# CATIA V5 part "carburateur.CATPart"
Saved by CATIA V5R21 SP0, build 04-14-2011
Part number: carburateur
Material "Aluminium": density 2710 kg/m3, Young's modulus 7e+10 Pa, Poisson ratio 0.346, thermal expansion 2.36e-05 1/K
Material "Aluminium": density 2710 kg/m3, Young's modulus 7e+10 Pa, Poisson ratio 0.346, thermal expansion 2.36e-05 1/K
Bounding box of the stored display mesh (mm): x -7.747 to 7, y -20 to 18, z -16 to 12
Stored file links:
  C:\Users\Olivier\Desktop\redaction CATIA (local)\CATIA\DONNEES\Exercice assemblage 3 (Pompe de ventilation)\carburateur.CATPart
  C:\Program Files\Dassault Systemes\B21\win_b64\startup\materials\French\Catalog.CATMaterial
  C:\Users\Olivier\Desktop\redaction CATIA (local)\pompe à moteur de ventilation refait\Pompe_a_moteur_de_ventilation.CATProduct
  C:\Users\Olivier\Desktop\redaction CATIA (local)\pompe à moteur de ventilation refait\Ecrou a collerette M5.CATPart
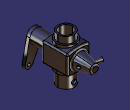
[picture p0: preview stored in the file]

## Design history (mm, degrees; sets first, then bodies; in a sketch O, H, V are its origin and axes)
Body1 (main body), material "Aluminium"
  Sketch1 on zx-plane, origin (0, 0, 0), H (-1, 0, 0), V (0, 0, 1)
    line L1 (7, 5.8379) -> (7, -5.8379)
    line L2 (-7, -5.8379) -> (-7, 5.8379)
    point P1 (7, 7)
    point P2 (7, -7)
    point P3 (-7, 7)
    arc A1 centre (0, -14.664) radius 21.664 from (-7, 5.8379) to (7, 5.8379) cw
    point P5 (-7, 5.8379)
    point P6 (7, 5.8379)
    point P7 (7, -5.8379)
    point P8 (-7, -5.8379)
    arc A2 centre (0, 14.664) radius 21.664 from (-7, -5.8379) to (7, -5.8379) ccw
    distance P1 P2 = 14
    distance P3 P1 = 14
    vertical: L1 V, L2 V
    equidistance: L1 L2 O
    symmetry: P6 P7 H, P5 P8 H, A1 A2 H
  Pad1: profile Sketch1, direction (0, 1, 0), length 8, mirrored extent
  Sketch2 on yz-plane, origin (0, 0, 0), H (0, 1, 0), V (0, 0, 1)
    projected line E1 (8, 5.8379) -> (8, -5.8379) from edge [face of Pad1 from Sketch1.L2 | end face of Pad1]
    projected line E2 (8, 5.0377) -> (8, 0) from edge [face of Pad1 from Sketch1.L2 | end face of Pad1]
    line L1 (8, 0) -> (18, 0)
    point P3 (8, 0)
    line L2 (18, 0) -> (18, 2.5)
    line L3 (18, 2.5) -> (8, 5.0377)
    point P6 (8, 5.0377)
    length L1 = 10
    length L2 = 2.5
    midpoint: P3 E1
    horizontal: L1 H
    vertical: L2 V
    coincidence: P6 E1
  Shaft1: profile Sketch2, axis Sketch2.L1, angle 360
  Sketch3 on start face of Pad1, origin (0, -8, 0), H (1, 0, 0), V (0, 0, 1)
    circle A1 centre (0, 0) radius 4.25
  Pad2: profile Sketch3, direction (0, -1, 0), length 10
  Sketch4 on end face of Pad2, origin (0, -18, 0), H (1, 0, 0), V (0, 0, 1)
    projected circle E1 centre (0, 0) radius 4.25 from edge [face of Pad2 from Sketch3.A1 | end face of Pad2]
    projected arc E2 centre (0, 0) radius 4.25 from (4.1613, 0.8638) to (-3.743, -2.0131) ccw from edge [face of Pad2 from Sketch3.A1 | end face of Pad2]
    circle A1 centre (4.7883, -13.1557) radius 1
    point P1 (4.7883, -13.1557)
    arc A2 centre (4.7883, -13.1557) radius 2.2354 from (2.8196, -14.2146) to (6.977, -12.7014) ccw
    line L1 (6.977, -12.7014) -> (4.1613, 0.8638)
    point P3 (4.1613, 0.8638)
    line L2 (2.8196, -14.2146) -> (-3.743, -2.0131)
    point P5 (-3.743, -2.0131)
    construction line L3 (0, 0) -> (4.7883, -13.1557)
    distance P1 O = 14
    angle L1 L2 = 16.547
    angle L3 H = 70
    tangency: L1 A2, L1 E1, L2 A2, L2 E1
    coincidence: E1 P3, E1 P5
    symmetry: L1 L2 L3
  Pad3: profile Sketch4, direction (0, -1, 0), length 2
  Sketch5 on xy-plane, origin (0, 0, 0), H (1, 0, 0), V (0, 1, 0)
    reference projected line E1 (-2.5, 18) -> (2.5, 18) from edge [face of Shaft1 from Sketch2.L3 | face of Shaft1 from Sketch2.L2]
    construction line L1 (-6.6056, 18) -> (-9.0298, 8.447)
    point P5 (-6.6056, 18)
    construction line L2 (-7.7542, 13.4735) -> (0, 11.5058)
    point P7 (-7.7542, 13.4735)
    point P9 (-7.1158, 15.9892)
    length L2 = 8
    coincidence: P5 E1, P7 L1, P9 L1
  Plane1: type Tangent, Support face of Shaft1 from Sketch2.L3, RefPoint Sketch5.P9
  Sketch6 on Plane1, origin (-10.4973, 2.6639, 0), H (0.246, 0.9693, 0), V (0, 0, 1)
    circle A1 centre (12.4304, 0) radius 1.25
    point P2 (11.982, 0)
  Pad4: profile Sketch6, direction (0.9693, -0.246, 0), up to the existing solid (limit type 2)
  Sketch7 on xy-plane, origin (0, 0, 0), H (1, 0, 0), V (0, 1, 0)
    circle A1 centre (0, 0) radius 6
    circle A2 centre (0, 0) radius 5
  MultiPad1: profile Sketch7, domains (length 12 / length 16; length 8 / length 8)
  Sketch8 on xy-plane, origin (0, 0, 0), H (1, 0, 0), V (0, 1, 0)
    circle A1 centre (0, 0) radius 4
  Pocket1: profile Sketch8, direction (0, 0, -1), length 26, mirrored extent
  Sketch9 on zx-plane, origin (0, 0, 0), H (-1, 0, 0), V (0, 0, 1)
    circle A1 centre (0, -13) radius 1.5
    point P1 (0, -13)
    reference projected line E1 (-6, -8) -> (6, -8) from edge [face of MultiPad1 | face of MultiPad1 from Sketch7.A1]
    distance E1 P1 = 5
    coincidence: P1 V
  Pocket2: profile Sketch9, direction (0, -1, 0), length 12, mirrored extent
  Sketch10 on xy-plane, origin (0, 0, 0), H (1, 0, 0), V (0, 1, 0)
    projected line E1 (-7, 8) -> (7, 8) from edge [face of Pad1 from Sketch1.A1 | end face of Pad1]
    projected line E2 (-3.7002, 8) -> (-1.6252, 8) from edge [face of Pad1 from Sketch1.A1 | end face of Pad1]
    projected line E3 (-2.5, 18) -> (2.5, 18) from edge [face of Shaft1 from Sketch2.L3 | face of Shaft1 from Sketch2.L2]
    line L1 (0, 16.8198) -> (0, 2.4964)
    point P5 (0, 18)
    line L2 (-1.6087, 16.8198) -> (-3.7002, 8)
    point P6 (-3.7002, 8)
    line L3 (-1.6252, 8) -> (-1.6252, 2.4964)
    point P7 (-1.6252, 8)
    line L4 (-1.6252, 2.4964) -> (0, 2.4964)
    line L5 (0, 16.8198) -> (-1.6087, 16.8198)
    midpoint: P5 E3
    vertical: L1 V, L3 V
    coincidence: P6 E1, P7 E1
    horizontal: L4 H, L5 H
  Groove1: profile Sketch10, axis Sketch10.L1, angle 360
  Sketch11 on start face of Pad4, origin (-10.4973, 2.6639, 0), H (-0.246, -0.9693, 0), V (0, 0, 1)
    reference projected circle E1 centre (-12.4304, 0) radius 1.25 from edge [start face of Pad4 | face of Pad4 from Sketch6.A1]
    circle A1 centre (-12.4304, 0) radius 1
    point P1 (-12.4304, 0)
    concentricity: P1 E1
  Pocket3: profile Sketch11, direction (0.9693, -0.246, 0), length 26
  Fillet1: radius 1, on edge [face of Pad1 from Sketch1.A1 | end face of Pad1]; edge [face of Pad1 from Sketch1.L2 | end face of Pad1]; edge [face of Pad1 from Sketch1.A2 | end face of Pad1]; edge [face of Pad1 from Sketch1.L1 | end face of Pad1]; edge [face of Pad1 from Sketch1.A1 | face of Pad1 from Sketch1.L1]; edge [face of Pad1 from Sketch1.L2 | face of Pad1 from Sketch1.A1]; edge [face of Pad1 from Sketch1.A2 | face of Pad1 from Sketch1.L2]; edge [start face of Pad1 | face of Pad1 from Sketch1.L2]; edge [start face of Pad1 | face of Pad1 from Sketch1.A1]; edge [start face of Pad1 | face of Pad1 from Sketch1.L1]; edge [start face of Pad1 | face of Pad1 from Sketch1.A2]; edge [face of Pad1 from Sketch1.L1 | face of Pad1 from Sketch1.A2]; edge [face of Shaft1 from Sketch2.L3 | face of Shaft1 from Sketch2.L2]
  Fillet2: radius 1, on edge [end face of Pad1 | face of Shaft1 from Sketch2.L3]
